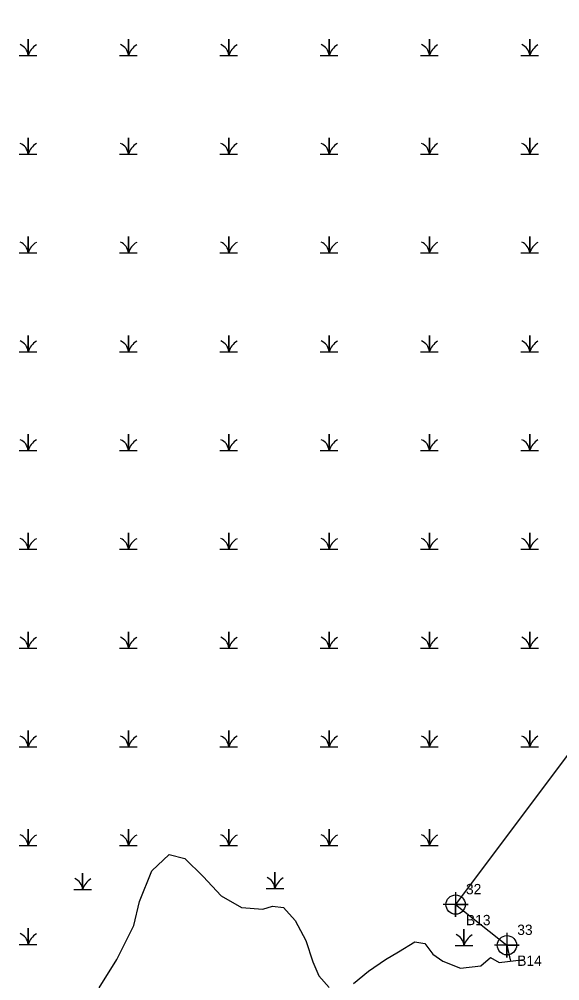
# Model space of a CAD drawing. Extents: x 2678633 to 2679425, y 623836 to 624637.
# Drawn here: x 2678840 to 2678971, y 624164.5 to 624397.6 of the extents above; entities that cross this region are included whole.
import ezdxf

# ---------------------------------------------------------------- set-up
doc = ezdxf.new("R2010")
doc.units = 0
for name, color, linetype in [('Exist Environmental Wetland Boundary', 7, 'Continuous'), ('Exist Environmental Wetland Boundary Cogo Comment', 7, 'Continuous'), ('Exist Environmental Wetland Boundary Cogo Number', 7, 'Continuous'), ('Exist Environmental Wetland Boundary Cogo Point CELL', 7, 'Continuous'), ('Exist Hydro Jurisdictional Stream or Body of Water NEU Mitigable', 7, 'Continuous'), ('Exist Hydro Swamp or Marsh', 7, 'Continuous')]:
    doc.layers.add(name, color=color, linetype=linetype)

msp = doc.modelspace()

# ---------------------------------------------------------------- linework, layer by layer
at = {"layer": 'Exist Environmental Wetland Boundary'}
msp.add_line((2678958.22, 624173.09), (2678959.12, 624169.24), dxfattribs=at)
msp.add_lwpolyline([(2679069.93, 624630.75), (2679087.52, 624604.07), (2679094.78, 624576.13), (2679101.43, 624567.27), (2679105.5, 624537.81), (2679136.33, 624529.73), (2679149.04, 624519.84), (2679171.39, 624510.69), (2679204.94, 624484.27), (2679140.71, 624428.23), (2679075.13, 624365.19), (2679029.64, 624305.05), (2678988.85, 624240.45), (2678945.79, 624182.95), (2678958.22, 624173.09)], dxfattribs=at)
at = {"layer": 'Exist Environmental Wetland Boundary Cogo Point CELL'}
for points in [[(2678945.79, 624185.95), (2678945.79, 624179.95), (2678945.79, 624182.95), (2678948.79, 624182.95), (2678942.79, 624182.95)], [(2678958.22, 624176.09), (2678958.22, 624170.09), (2678958.22, 624173.09), (2678961.22, 624173.09), (2678955.22, 624173.09)]]:
    msp.add_lwpolyline(points, dxfattribs=at)
for centre in [(2678945.79, 624182.95), (2678958.22, 624173.09)]:
    msp.add_circle(centre, 2.34, dxfattribs=at)
at = {"layer": 'Exist Hydro Jurisdictional Stream or Body of Water NEU Mitigable'}
for points in [[(2678859.43, 624162.76), (2678863.7, 624169.63), (2678867.76, 624177.89), (2678869.21, 624183.72), (2678872.18, 624191.15), (2678876.35, 624195.09), (2678880.16, 624194.14), (2678884.64, 624189.78), (2678888.93, 624185.09), (2678893.9, 624182.25), (2678899.06, 624181.85), (2678901.41, 624182.53), (2678904.05, 624182.26), (2678906.86, 624179.12), (2678909.45, 624174.25), (2678911.2, 624169.1), (2678912.62, 624165.68), (2678915.12, 624162.85)], [(2678921.06, 624163.85), (2678924.65, 624166.83), (2678928.77, 624169.62), (2678931.96, 624171.48), (2678935.87, 624173.94), (2678938.31, 624173.51), (2678940.26, 624170.96), (2678942.65, 624169.24), (2678947, 624167.51), (2678951.92, 624168.06), (2678954.25, 624170.08), (2678956.3, 624168.93), (2678962.38, 624169.6)]]:
    msp.add_lwpolyline(points, dxfattribs=at)
at = {"layer": 'Exist Hydro Swamp or Marsh'}
for p, q in [((2678855.38, 624188.41), (2678855.38, 624188.41)), ((2678901.99, 624188.64), (2678901.99, 624188.64)), ((2678947.81, 624174.82), (2678947.81, 624174.82))]:
    msp.add_line(p, q, dxfattribs=at)
for points in [[(2678840.03, 624388.85), (2678842.18, 624388.85), (2678842.18, 624392.8), (2678842.18, 624388.85), (2678844.33, 624388.85)], [(2678864.34, 624388.85), (2678866.49, 624388.85), (2678866.49, 624392.8), (2678866.49, 624388.85), (2678868.64, 624388.85)], [(2678888.65, 624388.85), (2678890.8, 624388.85), (2678890.8, 624392.8), (2678890.8, 624388.85), (2678892.95, 624388.85)], [(2678912.97, 624388.85), (2678915.12, 624388.85), (2678915.12, 624392.8), (2678915.12, 624388.85), (2678917.27, 624388.85)], [(2678937.28, 624388.85), (2678939.43, 624388.85), (2678939.43, 624392.8), (2678939.43, 624388.85), (2678941.58, 624388.85)], [(2678961.59, 624388.85), (2678963.74, 624388.85), (2678963.74, 624392.8), (2678963.74, 624388.85), (2678965.89, 624388.85)], [(2678840.03, 624364.9), (2678842.18, 624364.9), (2678842.18, 624368.85), (2678842.18, 624364.9), (2678844.33, 624364.9)], [(2678864.34, 624364.9), (2678866.49, 624364.9), (2678866.49, 624368.85), (2678866.49, 624364.9), (2678868.64, 624364.9)], [(2678888.65, 624364.9), (2678890.8, 624364.9), (2678890.8, 624368.85), (2678890.8, 624364.9), (2678892.95, 624364.9)], [(2678912.97, 624364.9), (2678915.12, 624364.9), (2678915.12, 624368.85), (2678915.12, 624364.9), (2678917.27, 624364.9)], [(2678937.28, 624364.9), (2678939.43, 624364.9), (2678939.43, 624368.85), (2678939.43, 624364.9), (2678941.58, 624364.9)], [(2678961.59, 624364.9), (2678963.74, 624364.9), (2678963.74, 624368.85), (2678963.74, 624364.9), (2678965.89, 624364.9)], [(2678840.03, 624340.95), (2678842.18, 624340.95), (2678842.18, 624344.9), (2678842.18, 624340.95), (2678844.33, 624340.95)], [(2678864.34, 624340.95), (2678866.49, 624340.95), (2678866.49, 624344.9), (2678866.49, 624340.95), (2678868.64, 624340.95)], [(2678888.65, 624340.95), (2678890.8, 624340.95), (2678890.8, 624344.9), (2678890.8, 624340.95), (2678892.95, 624340.95)], [(2678912.97, 624340.95), (2678915.12, 624340.95), (2678915.12, 624344.9), (2678915.12, 624340.95), (2678917.27, 624340.95)], [(2678937.28, 624340.95), (2678939.43, 624340.95), (2678939.43, 624344.9), (2678939.43, 624340.95), (2678941.58, 624340.95)], [(2678961.59, 624340.95), (2678963.74, 624340.95), (2678963.74, 624344.9), (2678963.74, 624340.95), (2678965.89, 624340.95)], [(2678840.03, 624317), (2678842.18, 624317), (2678842.18, 624320.95), (2678842.18, 624317), (2678844.33, 624317)], [(2678864.34, 624317), (2678866.49, 624317), (2678866.49, 624320.95), (2678866.49, 624317), (2678868.64, 624317)], [(2678888.65, 624317), (2678890.8, 624317), (2678890.8, 624320.95), (2678890.8, 624317), (2678892.95, 624317)], [(2678912.97, 624317), (2678915.12, 624317), (2678915.12, 624320.95), (2678915.12, 624317), (2678917.27, 624317)], [(2678937.28, 624317), (2678939.43, 624317), (2678939.43, 624320.95), (2678939.43, 624317), (2678941.58, 624317)], [(2678961.59, 624317), (2678963.74, 624317), (2678963.74, 624320.95), (2678963.74, 624317), (2678965.89, 624317)], [(2678840.03, 624293.05), (2678842.18, 624293.05), (2678842.18, 624297), (2678842.18, 624293.05), (2678844.33, 624293.05)], [(2678864.34, 624293.05), (2678866.49, 624293.05), (2678866.49, 624297), (2678866.49, 624293.05), (2678868.64, 624293.05)], [(2678888.65, 624293.05), (2678890.8, 624293.05), (2678890.8, 624297), (2678890.8, 624293.05), (2678892.95, 624293.05)], [(2678912.97, 624293.05), (2678915.12, 624293.05), (2678915.12, 624297), (2678915.12, 624293.05), (2678917.27, 624293.05)], [(2678937.28, 624293.05), (2678939.43, 624293.05), (2678939.43, 624297), (2678939.43, 624293.05), (2678941.58, 624293.05)], [(2678961.59, 624293.05), (2678963.74, 624293.05), (2678963.74, 624297), (2678963.74, 624293.05), (2678965.89, 624293.05)], [(2678840.03, 624269.1), (2678842.18, 624269.1), (2678842.18, 624273.05), (2678842.18, 624269.1), (2678844.33, 624269.1)], [(2678864.34, 624269.1), (2678866.49, 624269.1), (2678866.49, 624273.05), (2678866.49, 624269.1), (2678868.64, 624269.1)], [(2678888.65, 624269.1), (2678890.8, 624269.1), (2678890.8, 624273.05), (2678890.8, 624269.1), (2678892.95, 624269.1)], [(2678912.97, 624269.1), (2678915.12, 624269.1), (2678915.12, 624273.05), (2678915.12, 624269.1), (2678917.27, 624269.1)], [(2678937.28, 624269.1), (2678939.43, 624269.1), (2678939.43, 624273.05), (2678939.43, 624269.1), (2678941.58, 624269.1)], [(2678961.59, 624269.1), (2678963.74, 624269.1), (2678963.74, 624273.05), (2678963.74, 624269.1), (2678965.89, 624269.1)], [(2678840.03, 624245.15), (2678842.18, 624245.15), (2678842.18, 624249.1), (2678842.18, 624245.15), (2678844.33, 624245.15)], [(2678864.34, 624245.15), (2678866.49, 624245.15), (2678866.49, 624249.1), (2678866.49, 624245.15), (2678868.64, 624245.15)], [(2678888.65, 624245.15), (2678890.8, 624245.15), (2678890.8, 624249.1), (2678890.8, 624245.15), (2678892.95, 624245.15)], [(2678912.97, 624245.15), (2678915.12, 624245.15), (2678915.12, 624249.1), (2678915.12, 624245.15), (2678917.27, 624245.15)], [(2678937.28, 624245.15), (2678939.43, 624245.15), (2678939.43, 624249.1), (2678939.43, 624245.15), (2678941.58, 624245.15)], [(2678961.59, 624245.15), (2678963.74, 624245.15), (2678963.74, 624249.1), (2678963.74, 624245.15), (2678965.89, 624245.15)], [(2678840.03, 624221.2), (2678842.18, 624221.2), (2678842.18, 624225.15), (2678842.18, 624221.2), (2678844.33, 624221.2)], [(2678864.34, 624221.2), (2678866.49, 624221.2), (2678866.49, 624225.15), (2678866.49, 624221.2), (2678868.64, 624221.2)], [(2678888.65, 624221.2), (2678890.8, 624221.2), (2678890.8, 624225.15), (2678890.8, 624221.2), (2678892.95, 624221.2)], [(2678912.97, 624221.2), (2678915.12, 624221.2), (2678915.12, 624225.15), (2678915.12, 624221.2), (2678917.27, 624221.2)], [(2678937.28, 624221.2), (2678939.43, 624221.2), (2678939.43, 624225.15), (2678939.43, 624221.2), (2678941.58, 624221.2)], [(2678961.59, 624221.2), (2678963.74, 624221.2), (2678963.74, 624225.15), (2678963.74, 624221.2), (2678965.89, 624221.2)], [(2678840.03, 624197.25), (2678842.18, 624197.25), (2678842.18, 624201.2), (2678842.18, 624197.25), (2678844.33, 624197.25)], [(2678864.34, 624197.25), (2678866.49, 624197.25), (2678866.49, 624201.2), (2678866.49, 624197.25), (2678868.64, 624197.25)], [(2678888.65, 624197.25), (2678890.8, 624197.25), (2678890.8, 624201.2), (2678890.8, 624197.25), (2678892.95, 624197.25)], [(2678912.97, 624197.25), (2678915.12, 624197.25), (2678915.12, 624201.2), (2678915.12, 624197.25), (2678917.27, 624197.25)], [(2678937.28, 624197.25), (2678939.43, 624197.25), (2678939.43, 624201.2), (2678939.43, 624197.25), (2678941.58, 624197.25)], [(2678853.23, 624186.63), (2678855.38, 624186.63), (2678855.38, 624190.57), (2678855.38, 624186.63), (2678857.53, 624186.63)], [(2678899.84, 624186.86), (2678901.99, 624186.86), (2678901.99, 624190.81), (2678901.99, 624186.86), (2678904.14, 624186.86)], [(2678840.03, 624173.3), (2678842.18, 624173.3), (2678842.18, 624177.25), (2678842.18, 624173.3), (2678844.33, 624173.3)], [(2678945.66, 624173.04), (2678947.81, 624173.04), (2678947.81, 624176.98), (2678947.81, 624173.04), (2678949.96, 624173.04)]]:
    msp.add_lwpolyline(points, dxfattribs=at)
for centre, radius, start, end in [((2678839.11, 624388.63), 3.07, 4.1403, 67.535), ((2678846.74, 624387.34), 4.81, 122.1274, 161.6222), ((2678863.42, 624388.63), 3.07, 4.1403, 67.535), ((2678871.05, 624387.34), 4.81, 122.1274, 161.6222), ((2678887.74, 624388.63), 3.07, 4.1403, 67.535), ((2678895.36, 624387.34), 4.81, 122.1274, 161.6222), ((2678912.05, 624388.63), 3.07, 4.1403, 67.535), ((2678919.68, 624387.34), 4.81, 122.1274, 161.6222), ((2678936.36, 624388.63), 3.07, 4.1403, 67.535), ((2678943.99, 624387.34), 4.81, 122.1274, 161.6222), ((2678960.67, 624388.63), 3.07, 4.1403, 67.535), ((2678968.3, 624387.34), 4.81, 122.1274, 161.6222), ((2678839.11, 624364.68), 3.07, 4.1403, 67.535), ((2678846.74, 624363.39), 4.81, 122.1274, 161.6222), ((2678863.42, 624364.68), 3.07, 4.1403, 67.535), ((2678871.05, 624363.39), 4.81, 122.1274, 161.6222), ((2678887.74, 624364.68), 3.07, 4.1403, 67.535), ((2678895.36, 624363.39), 4.81, 122.1274, 161.6222), ((2678912.05, 624364.68), 3.07, 4.1403, 67.535), ((2678919.68, 624363.39), 4.81, 122.1274, 161.6222), ((2678936.36, 624364.68), 3.07, 4.1403, 67.535), ((2678943.99, 624363.39), 4.81, 122.1274, 161.6222), ((2678960.67, 624364.68), 3.07, 4.1403, 67.535), ((2678968.3, 624363.39), 4.81, 122.1274, 161.6222), ((2678839.11, 624340.73), 3.07, 4.1403, 67.535), ((2678846.74, 624339.44), 4.81, 122.1274, 161.6222), ((2678863.42, 624340.73), 3.07, 4.1403, 67.535), ((2678871.05, 624339.44), 4.81, 122.1274, 161.6222), ((2678887.74, 624340.73), 3.07, 4.1403, 67.535), ((2678895.36, 624339.44), 4.81, 122.1274, 161.6222), ((2678912.05, 624340.73), 3.07, 4.1403, 67.535), ((2678919.68, 624339.44), 4.81, 122.1274, 161.6222), ((2678936.36, 624340.73), 3.07, 4.1403, 67.535), ((2678943.99, 624339.44), 4.81, 122.1274, 161.6222), ((2678960.67, 624340.73), 3.07, 4.1403, 67.535), ((2678968.3, 624339.44), 4.81, 122.1274, 161.6222), ((2678839.11, 624316.78), 3.07, 4.1403, 67.535), ((2678846.74, 624315.49), 4.81, 122.1274, 161.6222), ((2678863.42, 624316.78), 3.07, 4.1403, 67.535), ((2678871.05, 624315.49), 4.81, 122.1274, 161.6222), ((2678887.74, 624316.78), 3.07, 4.1403, 67.535), ((2678895.36, 624315.49), 4.81, 122.1274, 161.6222), ((2678912.05, 624316.78), 3.07, 4.1403, 67.535), ((2678919.68, 624315.49), 4.81, 122.1274, 161.6222), ((2678936.36, 624316.78), 3.07, 4.1403, 67.535), ((2678943.99, 624315.49), 4.81, 122.1274, 161.6222), ((2678960.67, 624316.78), 3.07, 4.1403, 67.535), ((2678968.3, 624315.49), 4.81, 122.1274, 161.6222), ((2678839.11, 624292.83), 3.07, 4.1403, 67.535), ((2678846.74, 624291.54), 4.81, 122.1274, 161.6222), ((2678863.42, 624292.83), 3.07, 4.1403, 67.535), ((2678871.05, 624291.54), 4.81, 122.1274, 161.6222), ((2678887.74, 624292.83), 3.07, 4.1403, 67.535), ((2678895.36, 624291.54), 4.81, 122.1274, 161.6222), ((2678912.05, 624292.83), 3.07, 4.1403, 67.535), ((2678919.68, 624291.54), 4.81, 122.1274, 161.6222), ((2678936.36, 624292.83), 3.07, 4.1403, 67.535), ((2678943.99, 624291.54), 4.81, 122.1274, 161.6222), ((2678960.67, 624292.83), 3.07, 4.1403, 67.535), ((2678968.3, 624291.54), 4.81, 122.1274, 161.6222), ((2678839.11, 624268.88), 3.07, 4.1403, 67.535), ((2678846.74, 624267.59), 4.81, 122.1274, 161.6222), ((2678863.42, 624268.88), 3.07, 4.1403, 67.535), ((2678871.05, 624267.59), 4.81, 122.1274, 161.6222), ((2678887.74, 624268.88), 3.07, 4.1403, 67.535), ((2678895.36, 624267.59), 4.81, 122.1274, 161.6222), ((2678912.05, 624268.88), 3.07, 4.1403, 67.535), ((2678919.68, 624267.59), 4.81, 122.1274, 161.6222), ((2678936.36, 624268.88), 3.07, 4.1403, 67.535), ((2678943.99, 624267.59), 4.81, 122.1274, 161.6222), ((2678960.67, 624268.88), 3.07, 4.1403, 67.535), ((2678968.3, 624267.59), 4.81, 122.1274, 161.6222), ((2678839.11, 624244.93), 3.07, 4.1403, 67.535), ((2678863.42, 624244.93), 3.07, 4.1403, 67.535), ((2678887.74, 624244.93), 3.07, 4.1403, 67.535), ((2678912.05, 624244.93), 3.07, 4.1403, 67.535), ((2678936.36, 624244.93), 3.07, 4.1403, 67.535), ((2678960.67, 624244.93), 3.07, 4.1403, 67.535), ((2678846.74, 624243.64), 4.81, 122.1274, 161.6222), ((2678871.05, 624243.64), 4.81, 122.1274, 161.6222), ((2678895.36, 624243.64), 4.81, 122.1274, 161.6222), ((2678919.68, 624243.64), 4.81, 122.1274, 161.6222), ((2678943.99, 624243.64), 4.81, 122.1274, 161.6222), ((2678968.3, 624243.64), 4.81, 122.1274, 161.6222), ((2678839.11, 624220.98), 3.07, 4.1403, 67.535), ((2678846.74, 624219.69), 4.81, 122.1274, 161.6222), ((2678863.42, 624220.98), 3.07, 4.1403, 67.535), ((2678871.05, 624219.69), 4.81, 122.1274, 161.6222), ((2678887.74, 624220.98), 3.07, 4.1403, 67.535), ((2678895.36, 624219.69), 4.81, 122.1274, 161.6222), ((2678912.05, 624220.98), 3.07, 4.1403, 67.535), ((2678919.68, 624219.69), 4.81, 122.1274, 161.6222), ((2678936.36, 624220.98), 3.07, 4.1403, 67.535), ((2678943.99, 624219.69), 4.81, 122.1274, 161.6222), ((2678960.67, 624220.98), 3.07, 4.1403, 67.535), ((2678968.3, 624219.69), 4.81, 122.1274, 161.6222), ((2678839.11, 624197.03), 3.07, 4.1403, 67.535), ((2678846.74, 624195.74), 4.81, 122.1274, 161.6222), ((2678863.42, 624197.03), 3.07, 4.1403, 67.535), ((2678871.05, 624195.74), 4.81, 122.1274, 161.6222), ((2678887.74, 624197.03), 3.07, 4.1403, 67.535), ((2678895.36, 624195.74), 4.81, 122.1274, 161.6222), ((2678912.05, 624197.03), 3.07, 4.1403, 67.535), ((2678919.68, 624195.74), 4.81, 122.1274, 161.6222), ((2678936.36, 624197.03), 3.07, 4.1403, 67.535), ((2678943.99, 624195.74), 4.81, 122.1274, 161.6222), ((2678898.92, 624186.64), 3.07, 4.1403, 67.535), ((2678852.32, 624186.41), 3.07, 4.1403, 67.535), ((2678859.94, 624185.11), 4.81, 122.1274, 161.6222), ((2678906.55, 624185.35), 4.81, 122.1274, 161.6222), ((2678839.11, 624173.08), 3.07, 4.1403, 67.535), ((2678846.74, 624171.79), 4.81, 122.1274, 161.6222), ((2678944.74, 624172.82), 3.07, 4.1403, 67.535), ((2678952.37, 624171.52), 4.81, 122.1274, 161.6222)]:
    msp.add_arc(centre, radius, start, end, dxfattribs=at)

# ---------------------------------------------------------------- texts
at = {"layer": 'Exist Environmental Wetland Boundary Cogo Comment'}
for s, p in [('B13', (2678948.29, 624177.95)), ('B14', (2678960.72, 624168.09))]:
    msp.add_text(s, height=2.5, dxfattribs=at).set_placement(p)
at = {"layer": 'Exist Environmental Wetland Boundary Cogo Number'}
for s, p in [('32', (2678948.29, 624185.45)), ('33', (2678960.72, 624175.59))]:
    msp.add_text(s, height=2.5, dxfattribs=at).set_placement(p)

doc.saveas('drawing.dxf')
